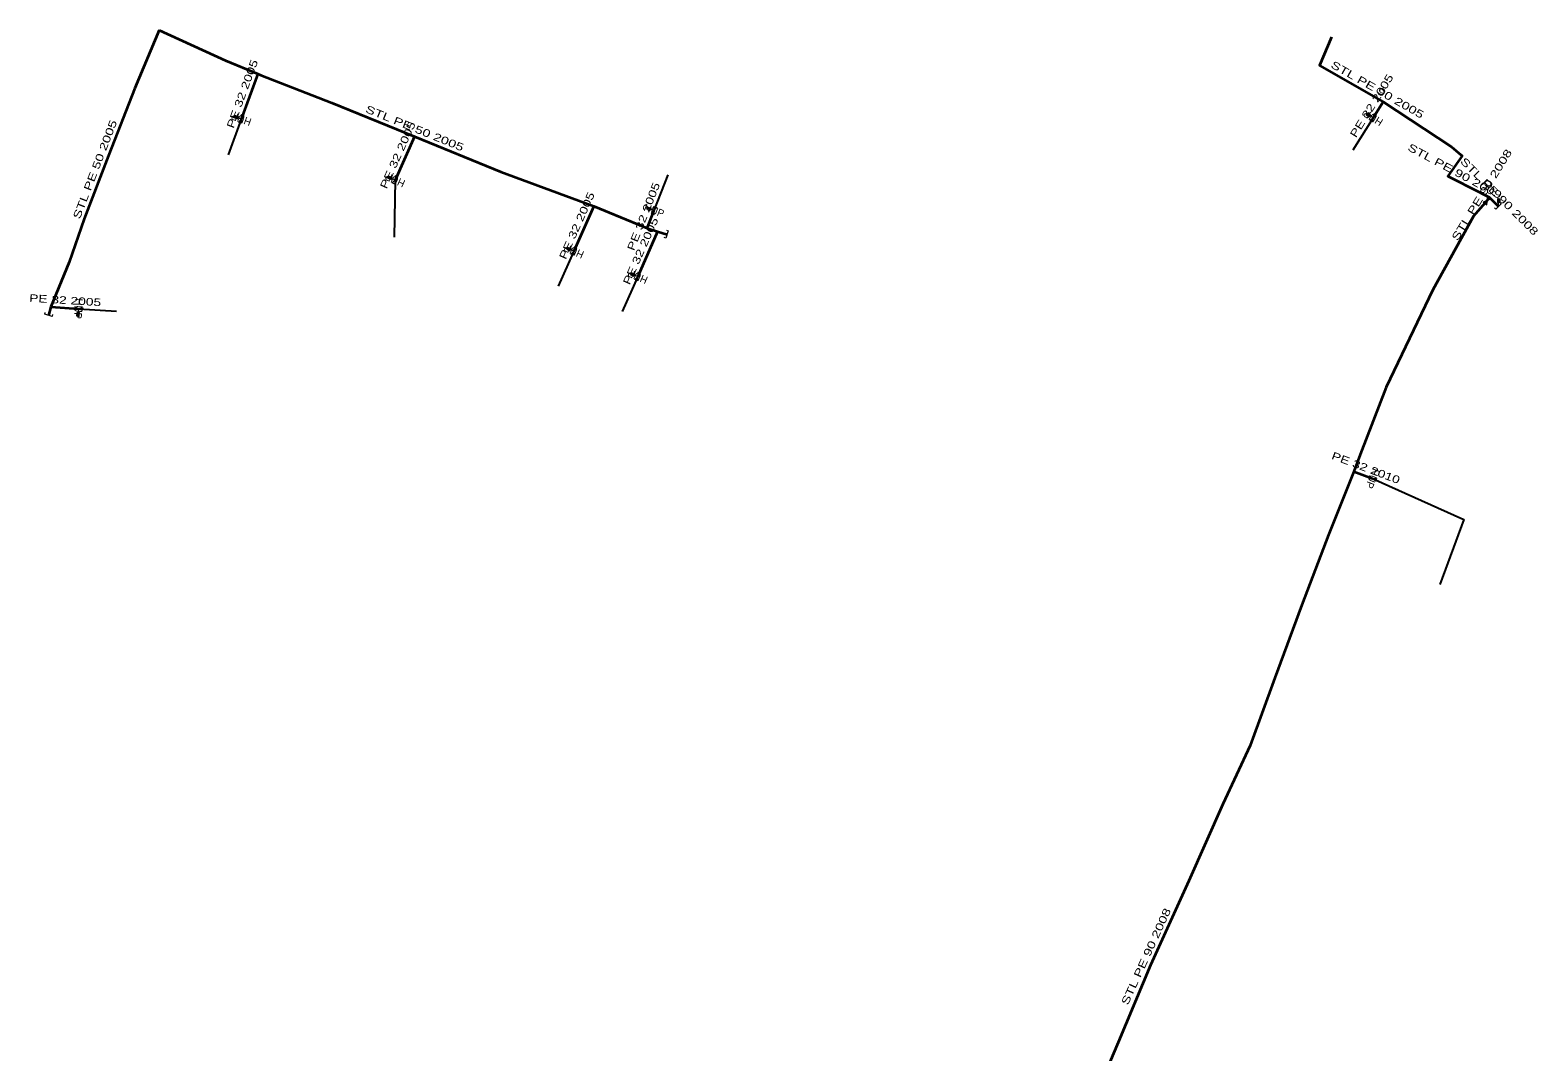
# Model space of a CAD drawing. Extents: x -737484 to -734496, y -1033882 to -1030666.
# Drawn here: x -737160.2 to -736962.7, y -1030926.7 to -1030792.9 of the extents above; entities that cross this region are included whole.
import ezdxf
from ezdxf.enums import TextEntityAlignment as Align

# ---------------------------------------------------------------- set-up
doc = ezdxf.new("R2010")
doc.units = 0
doc.header["$LTSCALE"] = 0.4
for name, color, linetype, lineweight in [('1', 7, 'Continuous', 13), ('22', 7, 'Continuous', 25), ('5', 7, 'Continuous', 35), ('7', 7, 'Continuous', 35)]:
    doc.layers.add(name, color=color, linetype=linetype, lineweight=lineweight)
doc.layers.add('2', color=7, linetype='Continuous')

msp = doc.modelspace()

# ---------------------------------------------------------------- linework, layer by layer
at = {"layer": '1'}
for p, q in [((-737133.072, -1030804.263), (-737133.401, -1030804.144)), ((-737132.558, -1030804.531), (-737133.027, -1030804.359)), ((-736984.754, -1030804.01), (-736985.051, -1030803.825)), ((-736984.307, -1030804.379), (-736984.731, -1030804.114)), ((-737112.917, -1030812.223), (-737113.237, -1030812.081)), ((-737112.423, -1030812.526), (-737112.879, -1030812.322)), ((-737078.996, -1030816.241), (-737079.323, -1030816.116)), ((-737078.487, -1030816.518), (-737078.953, -1030816.338)), ((-736967.87, -1030815.99), (-736967.87, -1030815.49)), ((-736967.795, -1030815.415), (-736967.795, -1030815.065)), ((-737089.49, -1030821.547), (-737089.81, -1030821.405)), ((-737088.996, -1030821.85), (-737089.452, -1030821.646)), ((-737081.129, -1030824.874), (-737081.449, -1030824.732)), ((-737080.635, -1030825.177), (-737081.091, -1030824.973)), ((-737153.988, -1030829.948), (-737154.013, -1030830.297)), ((-737153.874, -1030829.38), (-737153.908, -1030829.878))]:
    msp.add_line(p, q, dxfattribs=at)
for points in [[(-737133.497, -1030804.188), (-737133.548, -1030804.329), (-737133.079, -1030804.5), (-737133.027, -1030804.359)], [(-737133.497, -1030804.188), (-737133.446, -1030804.048), (-737132.976, -1030804.219), (-737133.027, -1030804.359)], [(-737133.449, -1030804.167), (-737133.423, -1030804.096), (-737133.024, -1030804.242), (-737133.049, -1030804.312)], [(-737132.541, -1030805.069), (-737132.916, -1030804.932), (-737132.199, -1030804.129), (-737132.574, -1030803.992)], [(-736985.155, -1030803.849), (-736985.234, -1030803.976), (-736984.81, -1030804.241), (-736984.731, -1030804.114)], [(-736985.155, -1030803.849), (-736985.075, -1030803.721), (-736984.651, -1030803.986), (-736984.731, -1030804.114)], [(-736985.103, -1030803.837), (-736985.063, -1030803.774), (-736984.703, -1030803.999), (-736984.742, -1030804.063)], [(-736984.402, -1030804.909), (-736984.741, -1030804.697), (-736983.872, -1030804.06), (-736984.211, -1030803.848)], [(-737113.336, -1030812.119), (-737113.397, -1030812.256), (-737112.94, -1030812.459), (-737112.879, -1030812.322)], [(-737113.336, -1030812.119), (-737113.275, -1030811.982), (-737112.818, -1030812.185), (-737112.879, -1030812.322)], [(-737113.286, -1030812.1), (-737113.256, -1030812.032), (-737112.868, -1030812.205), (-737112.898, -1030812.273)], [(-737112.443, -1030813.064), (-737112.809, -1030812.901), (-737112.036, -1030812.15), (-737112.402, -1030811.987)], [(-736969.298, -1030814.63), (-736968.819, -1030814.991), (-736969.9, -1030815.428), (-736969.421, -1030815.789)], [(-737079.42, -1030816.159), (-737079.474, -1030816.299), (-737079.007, -1030816.478), (-737078.953, -1030816.338)], [(-737079.42, -1030816.159), (-737079.366, -1030816.019), (-737078.9, -1030816.198), (-737078.953, -1030816.338)], [(-737079.371, -1030816.138), (-737079.344, -1030816.068), (-737078.948, -1030816.22), (-737078.975, -1030816.291)], [(-737078.494, -1030815.979), (-737078.121, -1030816.122), (-737078.852, -1030816.913), (-737078.479, -1030817.056)], [(-736967.87, -1030814.99), (-736968.02, -1030814.99), (-736968.02, -1030815.49), (-736967.87, -1030815.49)], [(-736967.87, -1030814.99), (-736967.72, -1030814.99), (-736967.72, -1030815.49), (-736967.87, -1030815.49)], [(-736967.833, -1030815.028), (-736967.758, -1030815.028), (-736967.758, -1030815.453), (-736967.833, -1030815.453)], [(-737089.909, -1030821.443), (-737089.97, -1030821.58), (-737089.513, -1030821.783), (-737089.452, -1030821.646)], [(-737089.909, -1030821.443), (-737089.848, -1030821.306), (-737089.391, -1030821.509), (-737089.452, -1030821.646)], [(-737089.859, -1030821.424), (-737089.829, -1030821.356), (-737089.441, -1030821.529), (-737089.471, -1030821.597)], [(-737089.016, -1030822.388), (-737089.382, -1030822.225), (-737088.609, -1030821.474), (-737088.975, -1030821.311)], [(-737081.548, -1030824.77), (-737081.609, -1030824.907), (-737081.152, -1030825.11), (-737081.091, -1030824.973)], [(-737081.548, -1030824.77), (-737081.487, -1030824.633), (-737081.03, -1030824.836), (-737081.091, -1030824.973)], [(-737081.498, -1030824.751), (-737081.468, -1030824.683), (-737081.08, -1030824.856), (-737081.11, -1030824.924)], [(-737080.655, -1030825.715), (-737081.021, -1030825.552), (-737080.248, -1030824.801), (-737080.614, -1030824.638)], [(-737153.361, -1030829.215), (-737153.389, -1030829.614), (-737154.358, -1030829.145), (-737154.386, -1030829.544)], [(-737153.943, -1030830.377), (-737154.093, -1030830.367), (-737154.058, -1030829.868), (-737153.908, -1030829.878)], [(-737153.978, -1030830.337), (-737154.052, -1030830.331), (-737154.023, -1030829.907), (-737153.948, -1030829.913)], [(-737153.943, -1030830.377), (-737153.794, -1030830.388), (-737153.759, -1030829.889), (-737153.908, -1030829.878)], [(-736983.851, -1030851.612), (-736983.994, -1030851.985), (-736984.785, -1030851.254), (-736984.928, -1030851.627)]]:
    msp.add_lwpolyline(points, close=True, dxfattribs=at)
for points in [[(-736967.693, -1030815.459), (-736967.516, -1030815.636), (-736968.223, -1030816.343), (-736968.4, -1030816.166)], [(-737076.876, -1030819.114), (-737076.637, -1030819.187), (-737076.93, -1030820.144), (-737077.169, -1030820.071)], [(-737157.267, -1030830.151), (-737157.336, -1030830.391), (-737158.297, -1030830.116), (-737158.228, -1030829.875)]]:
    msp.add_lwpolyline(points, dxfattribs=at)
at = {"layer": '22'}
for p, q in [((-737132.558, -1030804.531), (-737134.271, -1030809.228)), ((-736984.307, -1030804.379), (-736986.942, -1030808.628)), ((-737112.423, -1030812.526), (-737112.518, -1030820.004)), ((-737078.487, -1030816.518), (-737076.661, -1030811.863)), ((-737088.996, -1030821.85), (-737091.03, -1030826.418)), ((-737080.635, -1030825.177), (-737082.656, -1030829.75)), ((-737153.874, -1030829.38), (-737148.884, -1030829.696))]:
    msp.add_line(p, q, dxfattribs=at)
msp.add_lwpolyline([(-736984.39, -1030851.62), (-736972.41, -1030856.978), (-736975.585, -1030865.511)], dxfattribs=at)
at = {"layer": '5'}
for q in [(-736969.36, -1030815.21), (-736967.87, -1030815.99)]:
    msp.add_line((-736969.09, -1030814.77), q, dxfattribs=at)
for points in [[(-737143.332, -1030792.892), (-737146.483, -1030800.501), (-737149.952, -1030809.321), (-737153.13, -1030817.608), (-737155.112, -1030823.303), (-737157.494, -1030829.151), (-737157.817, -1030830.254)], [(-737143.332, -1030792.892), (-737134.635, -1030796.877), (-737130.405, -1030798.628), (-737129.981, -1030798.787), (-737120.69, -1030802.412), (-737109.87, -1030806.807), (-737098.546, -1030811.444), (-737086.376, -1030815.965), (-737079.387, -1030818.812), (-737078.028, -1030819.277), (-737076.784, -1030819.666)], [(-736989.77, -1030793.814), (-736991.308, -1030797.523), (-736982.993, -1030802.26), (-736974.05, -1030808.18)], [(-736974.05, -1030808.18), (-736973.13, -1030808.98), (-736972.65, -1030809.37), (-736974.53, -1030812), (-736973.56, -1030812.52), (-736969.09, -1030814.77)], [(-736969.36, -1030815.21), (-736971.17, -1030817.24), (-736976.5, -1030826.9), (-736982.61, -1030839.66), (-736986.02, -1030848.46), (-736986.83, -1030850.7), (-736990.16, -1030859.01), (-736993.65, -1030868.15), (-736997.16, -1030877.72), (-737000.4, -1030886.58), (-737003.99, -1030894.3), (-737008.44, -1030904.32), (-737013.46, -1030915.36), (-737017.71, -1030925.52), (-737019.88, -1030930.64)]]:
    msp.add_lwpolyline(points, dxfattribs=at)
at = {"layer": '7'}
for p, q in [((-737130.405, -1030798.628), (-737132.558, -1030804.531)), ((-736982.993, -1030802.26), (-736984.307, -1030804.379)), ((-737109.87, -1030806.807), (-737112.423, -1030812.526)), ((-737086.376, -1030815.965), (-737088.996, -1030821.85)), ((-737079.387, -1030818.812), (-737078.487, -1030816.518)), ((-737078.028, -1030819.277), (-737080.635, -1030825.177)), ((-737157.494, -1030829.151), (-737153.874, -1030829.38)), ((-736986.83, -1030850.7), (-736984.39, -1030851.62))]:
    msp.add_line(p, q, dxfattribs=at)

# ---------------------------------------------------------------- texts
at = {"layer": '2', "width": 0.95}
for rotation, p in [(160, (-737132.3865, -1030804.0603)), (148, (-736984.0415, -1030803.9547)), (156, (-737112.2191, -1030812.0683)), (339, (-737078.6657, -1030816.9843)), (156, (-737088.7921, -1030821.3923)), (156, (-737080.4311, -1030824.7193)), (266, (-737154.3726, -1030829.3446)), (249, (-736984.8563, -1030851.4403))]:
    msp.add_text('HUP', height=1, rotation=rotation, dxfattribs=at).set_placement(p, align=Align.CENTER)
at = {"layer": '5', "width": 1.4}
for s, rotation, p in [('STL PE 90 2005', 330.33, (-736983.9875, -1030801.1175)), ('STL PE 50 2005', 337.893, (-737110.0257, -1030806.2036)), ('STL PE 50 2005', 69.019, (-737151.2524, -1030811.315)), ('STL PE 90 2009', 331.805, (-736973.8377, -1030811.8028)), ('STL PE 90 2008', 58.465, (-736969.6506, -1030814.728)), ('STL PE 90 2008', 315, (-736968.1256, -1030815.0264)), ('STL PE 90 2008', 65.548, (-737013.5914, -1030914.4405))]:
    msp.add_text(s, height=1, rotation=rotation, dxfattribs=at).set_placement(p, align=Align.CENTER)
at = {"layer": '7', "width": 1.35}
for s, rotation, p in [('PE 32 2005', 69.962, (-737131.9507, -1030801.4078)), ('PE 32 2005', 58.197, (-736984.0739, -1030803.0555)), ('PE 32 2005', 65.944, (-737111.6028, -1030809.4618)), ('PE 32 2005', 68.579, (-737079.4023, -1030817.4816)), ('PE 32 2005', 66.001, (-737088.1422, -1030818.7039)), ('PE 32 2005', 66.161, (-737079.7885, -1030822.0246)), ('PE 32 2005', 356.38, (-737155.6516, -1030828.766)), ('PE 32 2010', 339.341, (-736985.4329, -1030850.692))]:
    msp.add_text(s, height=1, rotation=rotation, dxfattribs=at).set_placement(p, align=Align.CENTER)

doc.saveas('drawing.dxf')
